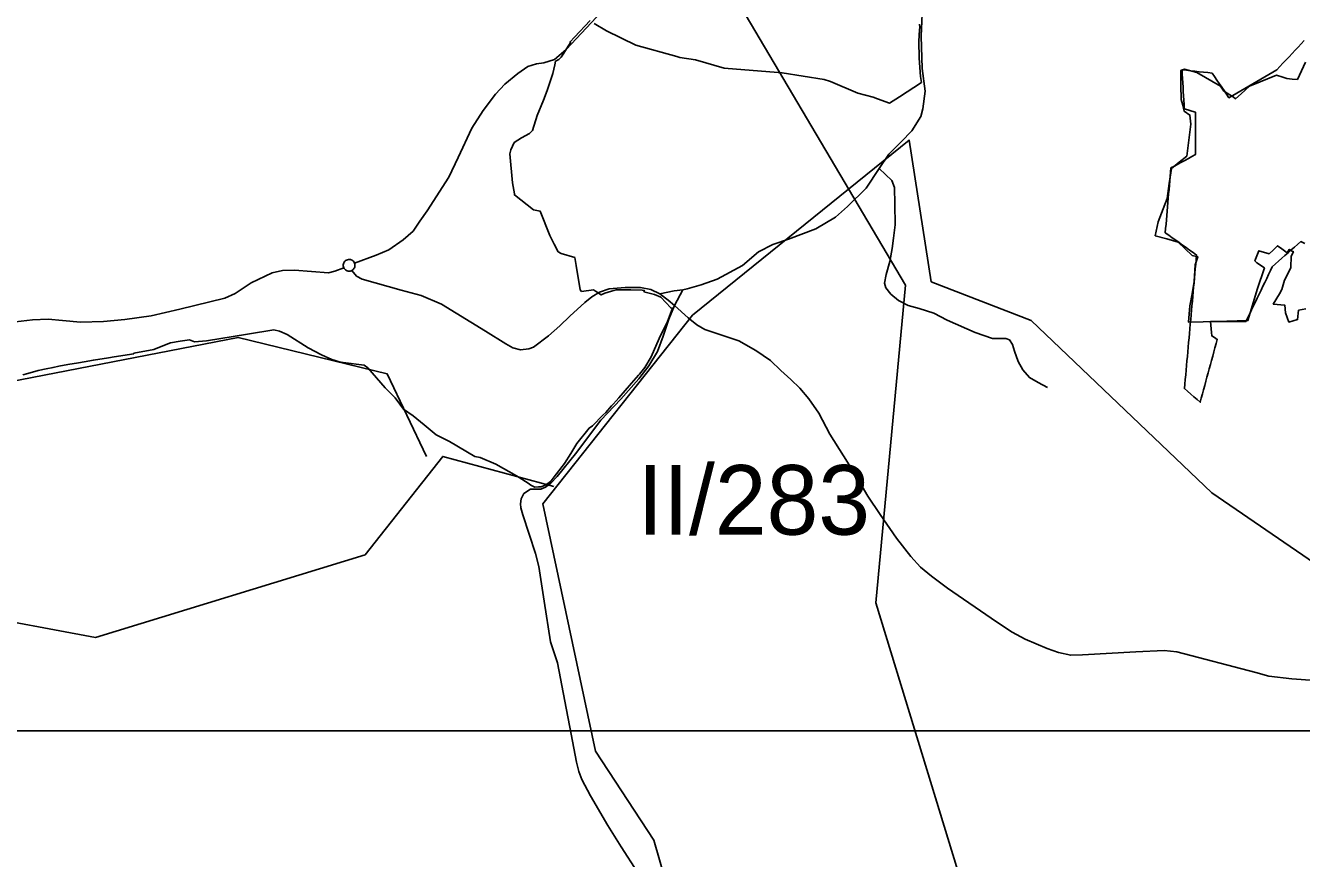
# Model space of a CAD drawing. Extents: x -789162 to -606354, y -1062736 to -945481.
# Drawn here: x -683055 to -680304, y -995752 to -993957 of the extents above; entities that cross this region are included whole.
import ezdxf

# ---------------------------------------------------------------- set-up
doc = ezdxf.new("R2010")
doc.units = 0
for name, color, linetype in [('_Rámeček', 7, 'Continuous'), ('_SIRSI VZTAHY_CYKLOTRASY MISTNI S', 7, 'Continuous'), ('_SIRSI VZTAHY_ELEKTRICKE VEDENI VN 400 kV S', 7, 'Continuous'), ('_SIRSI VZTAHY_NATURA_EVL', 7, 'Continuous'), ('_SIRSI VZTAHY_OP vodnich zdroju II stupne', 7, 'Continuous'), ('_SIRSI VZTAHY_SILNICE I a II TRIDY_STAV POPIS', 7, 'Continuous'), ('_SIRSI VZTAHY_SILNICE II TRIDY_STAV', 7, 'Continuous'), ('_SIRSI VZTAHY_SILNICE III TRIDY_STAV', 7, 'Continuous'), ('_SIRSI VZTAHY_USES_RBC_S', 7, 'Continuous')]:
    doc.layers.add(name, color=color, linetype=linetype)

msp = doc.modelspace()

# ---------------------------------------------------------------- linework, layer by layer
at = {"layer": '_Rámeček'}
msp.add_line((-694376.9, -995477.3), (-674375.7, -995477.3), dxfattribs=at)
at = {"layer": '_SIRSI VZTAHY_CYKLOTRASY MISTNI S'}
for points in [[(-682974.2, -993771.5), (-683110.7, -993925.7), (-683118.2, -994188.5), (-683179.3, -994387.8), (-683441.5, -994526.3), (-683506.5, -994765.8), (-683663.8, -994759), (-683629.6, -995114.9), (-683181.6, -995224.4), (-682904.6, -995275.7), (-682323.3, -995097.7), (-682155.7, -994885.6), (-681916.3, -994950.6)], [(-681623.1, -995982.1), (-681700.9, -995712.6), (-681826.6, -995521), (-681940.3, -994988), (-681617.1, -994580.8), (-681150.3, -994203.5), (-681102.5, -994509), (-680887, -994592.8), (-680498, -994964.1), (-680276.6, -995115.5), (-680003, -994855.4), (-679558.4, -994971.8), (-679565.3, -995118.9), (-679760.2, -995136), (-679746.5, -995262.6), (-679366.9, -995194.2), (-679185.7, -994971.8), (-678946.3, -995098.4), (-678529.1, -994999.2)], [(-682190.5, -994885.4), (-682275.4, -994707.6), (-682596.9, -994628.9), (-683089.3, -994724.8), (-683660.4, -994923.2)]]:
    msp.add_lwpolyline(points, dxfattribs=at)
at = {"layer": '_SIRSI VZTAHY_ELEKTRICKE VEDENI VN 400 kV S'}
msp.add_lwpolyline([(-678166.3, -997975), (-678439.4, -997795), (-678660.8, -997649.5), (-679002.5, -997425.1), (-679222.9, -997280.5), (-679622.1, -997017.8), (-679846.3, -996870.2), (-680073, -996721.2), (-680304.5, -996569.1), (-680758.3, -996270.5), (-680929.3, -996158), (-681000.1, -995927.1), (-681168, -995377.1), (-681221.7, -995201.1), (-681158.1, -994516.5), (-681411, -994089), (-681573.6, -993813.5), (-681729, -993549.7), (-682076.2, -992960.6), (-682198.7, -992719.4), (-682367.5, -992387.1)], dxfattribs=at)
at = {"layer": '_SIRSI VZTAHY_NATURA_EVL'}
msp.add_lwpolyline([(-680298.4, -993989.1), (-680305, -993996.1), (-680311.5, -994003.1), (-680318.1, -994010.1), (-680324.6, -994017.1), (-680331.2, -994024.1), (-680337.8, -994031.1), (-680344.3, -994038.1), (-680350.9, -994045.1), (-680357.4, -994052.1), (-680366.1, -994057.1), (-680374.7, -994062.1), (-680383.3, -994067.2), (-680391.9, -994072.2), (-680400.5, -994077.2), (-680409.2, -994082.2), (-680417.8, -994087.2), (-680426.4, -994092.2), (-680435, -994097.2), (-680443.6, -994102.2), (-680452.3, -994107.2), (-680460.9, -994112.3), (-680466, -994104.7), (-680471.2, -994097.1), (-680476.4, -994089.6), (-680481.5, -994082), (-680486.7, -994074.5), (-680491.8, -994066.9), (-680497, -994059.3), (-680506.2, -994058.3), (-680515.5, -994057.3), (-680524.8, -994056.2), (-680534.1, -994055.2), (-680543.4, -994054.2), (-680552.6, -994053.2), (-680561.9, -994052.1), (-680561.4, -994061.5), (-680560.9, -994070.8), (-680560.3, -994080.2), (-680559.8, -994089.5), (-680559.2, -994098.9), (-680558.7, -994108.2), (-680558.2, -994117.6), (-680557.6, -994127), (-680557.1, -994136.3), (-680549.1, -994138.7), (-680541.1, -994141.1), (-680533.1, -994143.5), (-680533.1, -994152.7), (-680533.1, -994161.8), (-680533.1, -994171), (-680533.1, -994180.1), (-680533.1, -994189.2), (-680533.1, -994198.4), (-680533.1, -994207.5), (-680533.1, -994216.7), (-680533.1, -994225.8), (-680533.1, -994234.9), (-680540.6, -994239.1), (-680548.2, -994243.2), (-680555.7, -994247.3), (-680563.3, -994251.4), (-680570.9, -994255.6), (-680578.4, -994259.7), (-680586, -994263.8), (-680586.8, -994273.1), (-680587.6, -994282.4), (-680588.4, -994291.7), (-680589.2, -994301), (-680590, -994310.3), (-680590.8, -994319.6), (-680591.6, -994328.9), (-680592.4, -994338.2), (-680593.2, -994347.5), (-680594, -994356.8), (-680594.8, -994366.1), (-680595.6, -994375.4), (-680596.4, -994384.7), (-680597.2, -994394), (-680598, -994403.3), (-680590.5, -994408.7), (-680583, -994414), (-680575.6, -994419.4), (-680568.1, -994424.7), (-680560.6, -994430.1), (-680553.1, -994435.4), (-680545.6, -994440.7), (-680538.1, -994446.1), (-680530.6, -994451.4), (-680531.5, -994461.4), (-680532.4, -994471.3), (-680533.3, -994481.2), (-680534.2, -994491.1), (-680535.1, -994501.1), (-680536, -994511), (-680536.9, -994520.9), (-680537.8, -994530.8), (-680538.7, -994540.8), (-680539.6, -994550.7), (-680540.5, -994560.6), (-680541.4, -994570.6), (-680542.3, -994580.5), (-680543.2, -994590.4), (-680544.1, -994600.3), (-680545, -994610.3), (-680545.9, -994620.2), (-680546.8, -994630.1), (-680547.7, -994640), (-680548.6, -994650), (-680549.5, -994659.9), (-680550.4, -994669.8), (-680551.3, -994679.7), (-680552.2, -994689.7), (-680553.1, -994699.6), (-680554, -994709.5), (-680554.9, -994719.4), (-680555.8, -994729.4), (-680556.7, -994739.3), (-680549.9, -994745.2), (-680543.2, -994751.1), (-680536.4, -994757), (-680529.6, -994762.9), (-680522.8, -994768.8), (-680520.4, -994759.7), (-680517.9, -994750.7), (-680515.5, -994741.7), (-680513, -994732.6), (-680510.5, -994723.6), (-680508.1, -994714.5), (-680505.6, -994705.5), (-680503.2, -994696.5), (-680500.7, -994687.4), (-680498.3, -994678.4), (-680495.8, -994669.3), (-680493.3, -994660.3), (-680490.9, -994651.3), (-680488.4, -994642.2), (-680486, -994633.2), (-680491.9, -994629.5), (-680497.8, -994625.8), (-680498.5, -994618.1), (-680499.2, -994610.3), (-680500, -994602.6), (-680500.7, -994594.9), (-680491.1, -994594.9), (-680481.6, -994594.9), (-680472, -994594.9), (-680462.4, -994594.9), (-680452.8, -994594.9), (-680443.2, -994594.9), (-680433.6, -994594.9), (-680424.1, -994594.9), (-680420, -994586.4), (-680416, -994578), (-680411.9, -994569.5), (-680407.8, -994561.1), (-680403.8, -994552.6), (-680399.7, -994544.2), (-680395.7, -994535.7), (-680391.6, -994527.3), (-680387.5, -994518.8), (-680383.5, -994510.4), (-680379.4, -994501.9), (-680375.4, -994493.5), (-680371.3, -994485), (-680367.3, -994476.6), (-680360.5, -994470.5), (-680353.7, -994464.5), (-680346.9, -994458.5), (-680340.1, -994452.5), (-680333.3, -994446.5), (-680326.5, -994440.4), (-680319.7, -994434.4), (-680312.9, -994428.4), (-680306.1, -994422.4), (-680297.4, -994426.7)], dxfattribs=at)
at = {"layer": '_SIRSI VZTAHY_OP vodnich zdroju II stupne'}
for points in [[(-683061.1, -994709.6), (-683050.3, -994706.7), (-683028.2, -994700.1), (-683011.1, -994696.8), (-682995.8, -994693.5), (-682983.8, -994691.2), (-682964.1, -994687.6), (-682940.8, -994683.5), (-682928.5, -994681.5), (-682909, -994678), (-682876.3, -994673), (-682864.5, -994671.2), (-682821.9, -994664.2), (-682821.6, -994662.7), (-682778.9, -994654.8), (-682769.8, -994651.7), (-682742.5, -994640.9), (-682721.6, -994637.4), (-682701.7, -994634.2), (-682691.3, -994638.2), (-682664.8, -994636.3), (-682576.7, -994621.9), (-682520, -994612.5), (-682507.5, -994615.3), (-682491.4, -994622.4), (-682446, -994651.5), (-682416.9, -994666.7), (-682394.7, -994676.6), (-682390, -994678.1), (-682379.3, -994681.5), (-682370.2, -994682.7), (-682325, -994688.8), (-682317.3, -994694.9), (-682279.7, -994737.4), (-682258.2, -994759.4), (-682240.5, -994784), (-682219.3, -994797.7), (-682196, -994817.3), (-682169.7, -994839.2), (-682141.2, -994853.2), (-682086.8, -994885.6), (-682075, -994888), (-682041, -994902.1), (-681996.8, -994927.3), (-681971.3, -994943.5), (-681966.1, -994947.6), (-681957.3, -994952), (-681949, -994951.2), (-681943.3, -994950.7), (-681935.1, -994947.8), (-681927.1, -994942.7), (-681922.2, -994938.3), (-681915.4, -994929.4), (-681893.5, -994900.6), (-681879.7, -994879.5), (-681866.4, -994857.3), (-681840.4, -994824.5), (-681832.7, -994819.5), (-681810.3, -994796.3), (-681804.5, -994790.6), (-681792.2, -994776.5), (-681788.7, -994773.2), (-681781.8, -994765.4), (-681776.3, -994759.1), (-681748.6, -994727.3), (-681733.5, -994710.4), (-681731.7, -994708.4), (-681720.1, -994693.8), (-681706.2, -994670.9), (-681689.5, -994631.2), (-681681.3, -994615.1), (-681671.1, -994594.6), (-681660.7, -994565.8), (-681664.2, -994565.5), (-681685.9, -994542.3), (-681699.2, -994536.8), (-681722, -994530.4), (-681721.1, -994527.7), (-681726.1, -994526.8), (-681750.4, -994526.4), (-681781.6, -994526.6), (-681792.2, -994529.1), (-681806.6, -994533.4), (-681813.9, -994537.3), (-681826.2, -994529.6), (-681831, -994526.3), (-681856.3, -994530), (-681859.6, -994526.4), (-681868.2, -994473.7), (-681871, -994456.9), (-681900.3, -994448), (-681907.2, -994444.5), (-681915.9, -994427.8), (-681924.9, -994409.1), (-681945.4, -994357.2), (-681959.9, -994353.9), (-682001.3, -994321.7), (-682001.4, -994319.5), (-682005.7, -994295.6), (-682011, -994233), (-682008.8, -994225), (-682001.5, -994209), (-681986.3, -994198.7), (-681968.4, -994189.5), (-681962.3, -994183), (-681952.3, -994150.4), (-681938.8, -994117.8), (-681930.7, -994096.7), (-681924.1, -994077.1), (-681922.1, -994071.2), (-681918.5, -994060.3), (-681913.8, -994041.3), (-681912.4, -994033.8), (-681905.6, -994029.7), (-681904, -994028.3), (-681900.4, -994025.2), (-681896.2, -994018.5), (-681883.6, -993998.7), (-681880, -993993), (-681881.3, -993991.8), (-681871.9, -993982), (-681837.8, -993945.6)], [(-681829.5, -993952), (-681802.6, -993968.2), (-681739.7, -993999.3), (-681651.3, -994023.3), (-681644.6, -994025.3), (-681611, -994030.9), (-681549, -994048.9), (-681432.9, -994057.9), (-681424.3, -994058.9), (-681333.6, -994073.4), (-681319.8, -994077.5), (-681261, -994102.3), (-681227.9, -994111.2), (-681218.2, -994114.7), (-681192.3, -994123.9), (-681171, -994110.6), (-681123.7, -994079.2), (-681125.4, -994066.3), (-681128.5, -994027.1), (-681129.2, -993990.4), (-681127.7, -993965.9), (-681127.3, -993960.9), (-681127.6, -993953.9)]]:
    msp.add_lwpolyline(points, dxfattribs=at)
at = {"layer": '_SIRSI VZTAHY_SILNICE II TRIDY_STAV'}
for points in [[(-682345.7, -994469.3), (-682346.6, -994467.4), (-682347.8, -994465.6), (-682349.3, -994464.1), (-682351, -994462.8), (-682352.9, -994461.8), (-682354.9, -994461.2), (-682357, -994461), (-682359.2, -994461), (-682361.3, -994461.5), (-682363.2, -994462.3), (-682365.1, -994463.4), (-682366.7, -994464.8), (-682368, -994466.5), (-682369.1, -994468.3), (-682369.8, -994470.3), (-682370.1, -994472.4), (-682370.2, -994474.5), (-682369.8, -994476.7), (-682369.1, -994478.7)], [(-683196.7, -994622.6), (-683179.1, -994616.2), (-683143.1, -994605.5), (-683108.2, -994599.7), (-683076.6, -994595.5), (-683039.9, -994590.8), (-683006.2, -994589.8), (-682975.4, -994592.3), (-682937, -994596.1), (-682886.8, -994594.8), (-682841.2, -994590.2), (-682784.4, -994582.6), (-682722.7, -994568), (-682625.3, -994544.2), (-682603, -994534.2), (-682568.6, -994511.1), (-682523.8, -994489.7), (-682501.1, -994485.1), (-682475.2, -994483.9), (-682402, -994490), (-682388.3, -994486.1), (-682369.1, -994478.7)], [(-682369.1, -994478.7), (-682368.1, -994480.5), (-682366.8, -994482.1), (-682365.3, -994483.5), (-682363.5, -994484.7), (-682361.6, -994485.5), (-682359.6, -994486), (-682357.6, -994486.2), (-682355.5, -994486), (-682353.5, -994485.5), (-682351.6, -994484.6)], [(-682351.6, -994484.6), (-682349.9, -994483.5), (-682348.4, -994482.2), (-682347.2, -994480.7), (-682346.2, -994479), (-682345.5, -994477.1), (-682345.1, -994475.2), (-682345, -994473.2), (-682345.2, -994471.2), (-682345.7, -994469.3)], [(-682351.6, -994484.6), (-682341.6, -994497.3), (-682329.7, -994503.2), (-682245.2, -994526.8), (-682202.6, -994538.7), (-682158.1, -994557.3), (-682063.8, -994615.5), (-682020, -994642.9), (-682004.7, -994651.3), (-681987.9, -994655.6), (-681969.9, -994653.8), (-681960.2, -994649.9), (-681927.9, -994625.6), (-681903.6, -994603.7), (-681882, -994583.1), (-681849.6, -994553.9), (-681834, -994541.3), (-681817.7, -994531.3), (-681797, -994524.2), (-681762.3, -994521.5), (-681729.3, -994521.5), (-681707.3, -994525.5), (-681687.9, -994534.9)], [(-681687.9, -994534.9), (-681669.8, -994548.6), (-681655.8, -994559.9)], [(-681655.8, -994559.9), (-681626.6, -994586.9), (-681608.2, -994602.1), (-681590.5, -994611.6), (-681517.1, -994636.5), (-681480.9, -994656.9), (-681449.4, -994679.1), (-681426.9, -994700.6), (-681405.6, -994719.7), (-681385.9, -994738.5), (-681366.2, -994761.4), (-681345.2, -994792.6), (-681320.9, -994837.6), (-681270.8, -994917.4), (-681239.4, -994970.9), (-681212.6, -995010.9), (-681177.8, -995061.7), (-681146.5, -995101.4), (-681125.9, -995124.3), (-681102.3, -995143.7), (-681067.5, -995169.8), (-680961.6, -995242.2), (-680928.1, -995264), (-680900.1, -995279.1), (-680852.4, -995299.5), (-680828.3, -995307.8), (-680802, -995314.1), (-680776.8, -995313.2), (-680661.8, -995306.5), (-680600.3, -995303.6), (-680573.3, -995306.9), (-680402.6, -995351.4), (-680374.8, -995359.2), (-680325, -995364.7), (-680275.6, -995368.4)]]:
    msp.add_lwpolyline(points, dxfattribs=at)
at = {"layer": '_SIRSI VZTAHY_SILNICE III TRIDY_STAV'}
for points in [[(-681214.9, -994265.1), (-681194, -994233.9), (-681167.2, -994207.1), (-681144.1, -994183.6), (-681125.1, -994152.5), (-681120.8, -994136.2), (-681115.8, -994098.5), (-681122.1, -994049.2), (-681124, -993979.3), (-681120.8, -993898.6), (-681115.6, -993867.5), (-681103.2, -993835.8), (-681091.9, -993801.8), (-681081.2, -993763.9), (-681077.9, -993735.3), (-681076.8, -993727.1), (-681080.7, -993715.3), (-681094.2, -993677), (-681107.7, -993645.3), (-681120, -993625.5), (-681133.4, -993609.5), (-681187.9, -993553.5), (-681240, -993506.9)], [(-682345.7, -994469.3), (-682299.4, -994451.9), (-682272.2, -994439.9), (-682240.9, -994418.7), (-682219.6, -994400.2), (-682205.1, -994378.2), (-682189, -994356.3), (-682142.8, -994283.9), (-682122.2, -994241.4), (-682093.4, -994178.2), (-682068.7, -994139.6), (-682042.2, -994104.5), (-682021.8, -994082.9), (-681993.8, -994060), (-681972.4, -994045.2), (-681953.7, -994039.2), (-681937.7, -994037.4), (-681914.9, -994030.3), (-681889.9, -994008.6), (-681824.4, -993938.7), (-681798.6, -993912.9)], [(-681214.9, -994265.1), (-681243.2, -994307.2), (-681282.8, -994346.8), (-681309.1, -994369.5), (-681351.6, -994394.7), (-681410.4, -994417.1), (-681444, -994428.9), (-681475.2, -994444.7), (-681509.3, -994473.9), (-681564.1, -994503.2), (-681598.4, -994515.6), (-681628.5, -994524.3), (-681637.8, -994526.4)], [(-681214.9, -994265.1), (-681187.8, -994291.1), (-681181.9, -994306.2), (-681181.3, -994341.5), (-681180.6, -994386.1), (-681184.2, -994414.9), (-681187.1, -994437.6), (-681191.8, -994465), (-681199.7, -994493.7), (-681203.3, -994512), (-681200.4, -994522), (-681189.7, -994536), (-681173.1, -994549.3), (-681152.2, -994560.1), (-681128.5, -994566.4), (-681097.3, -994576.7), (-681068.2, -994592.1), (-681007.8, -994618.3), (-680970.2, -994631.6), (-680941.5, -994631.6), (-680934, -994634.3), (-680927.2, -994644.5), (-680922.8, -994658.8), (-680915.5, -994680.9), (-680905.4, -994699.2), (-680890.9, -994715.5), (-680872.3, -994726.4), (-680851.6, -994736.8)], [(-681637.8, -994526.4), (-681656.8, -994528.3), (-681687.9, -994534.9)], [(-681655.8, -994559.9), (-681637.8, -994526.4)], [(-681655.8, -994559.9), (-681668.2, -994589.5), (-681680.5, -994626.5), (-681693.1, -994659.5), (-681711.1, -994690.3), (-681733.2, -994718.2), (-681771.5, -994762.3), (-681814.7, -994807.2), (-681869.3, -994880.2), (-681909.4, -994929.1), (-681922.7, -994943.1), (-681934.5, -994951.5), (-681944, -994955.8), (-681966.8, -994956.4), (-681981.1, -994965.7), (-681986.5, -994976.7), (-681988.2, -994987.5), (-681987.3, -994996), (-681983.4, -995011.7), (-681956.1, -995094.8), (-681948.4, -995122.8), (-681941.7, -995169.6), (-681937.4, -995197.3), (-681923.7, -995285.2), (-681908.1, -995330.1), (-681892.9, -995413), (-681878.6, -995484.1), (-681867.5, -995544.7), (-681862.7, -995564.7), (-681855.6, -995581.8), (-681837.1, -995617.2), (-681799.5, -995681.2), (-681770.9, -995727.2), (-681735.7, -995781.6)]]:
    msp.add_lwpolyline(points, dxfattribs=at)
at = {"layer": '_SIRSI VZTAHY_USES_RBC_S'}
msp.add_lwpolyline([(-680294.9, -994567.4), (-680310.6, -994570.5), (-680312.8, -994590.6), (-680331.4, -994596), (-680338.7, -994575.7), (-680340.4, -994559.2), (-680365.3, -994557.2), (-680352, -994535), (-680346.5, -994526), (-680340.7, -994505.7), (-680334.1, -994492.1), (-680327.5, -994478.4), (-680326.7, -994453.9), (-680321.7, -994444.3), (-680330.9, -994439.4), (-680335.6, -994446.7), (-680346.6, -994438.3), (-680355.8, -994431.5), (-680365.1, -994440.9), (-680374.2, -994448.6), (-680396, -994442.2), (-680404.7, -994463.9), (-680400.3, -994468.3), (-680384.2, -994479.2), (-680399.9, -994526), (-680409.9, -994559.4), (-680420, -994592.8), (-680488.1, -994594.5), (-680516.5, -994595.4), (-680547.9, -994596.2), (-680544.9, -994561), (-680540.4, -994534.8), (-680538.2, -994521.7), (-680535.9, -994508.6), (-680533.3, -994472.4), (-680527.8, -994455.6), (-680540.3, -994452.4), (-680555.4, -994438), (-680570.5, -994423.5), (-680595, -994416.6), (-680619.5, -994409.7), (-680613.6, -994380.1), (-680602.9, -994352), (-680594.2, -994329.3), (-680589.5, -994297.1), (-680584.8, -994264.9), (-680568, -994251.6), (-680551.3, -994238.3), (-680547, -994203.7), (-680542.6, -994169), (-680544.9, -994149.9), (-680557.3, -994141.6), (-680560.5, -994128.7), (-680563.8, -994115.9), (-680564.2, -994085), (-680564.6, -994054), (-680556.4, -994050.5), (-680529.9, -994057.9), (-680479, -994087.7), (-680471.5, -994098.2), (-680451.5, -994110.4), (-680446.8, -994114.5), (-680434.3, -994103.6), (-680416.2, -994087.7), (-680393.5, -994078.1), (-680358.1, -994063.7), (-680344.7, -994068), (-680335.9, -994070.8), (-680324.5, -994072), (-680313.2, -994072.8), (-680295.7, -994035.8)], dxfattribs=at)

# ---------------------------------------------------------------- texts
at = {"layer": '_SIRSI VZTAHY_SILNICE I a II TRIDY_STAV POPIS'}
msp.add_text('II/283', height=150, dxfattribs=at).set_placement((-681736.4, -995054.2))

doc.saveas('drawing.dxf')
